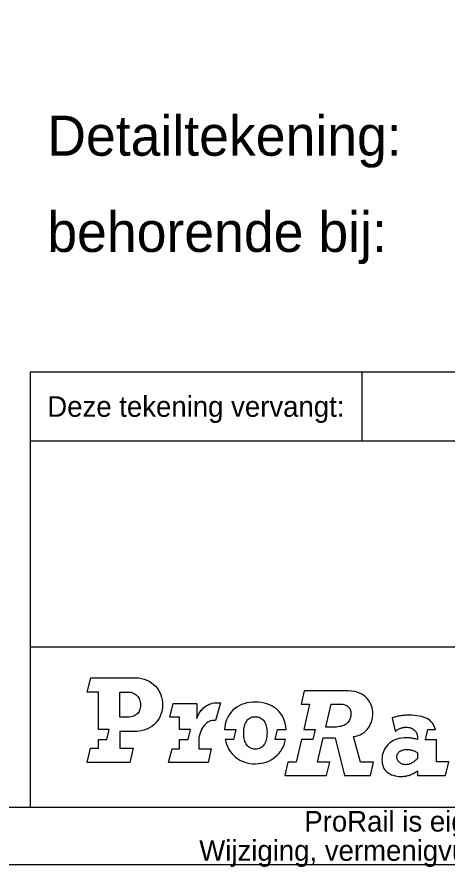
# Model space of a CAD drawing. Extents: x 0 to 1051, y 0 to 297.
# Drawn here: x 864.9 to 902.4, y -0.2 to 74 of the extents above; entities that cross this region are included whole.
import ezdxf

# ---------------------------------------------------------------- set-up
doc = ezdxf.new("R2010")
doc.units = 0
for name, color, linetype in [('KADER-LIJNEN-018', 7, 'Continuous'), ('KADER-LIJNEN-050', 7, 'Continuous'), ('TITEL-DETAIL', 7, 'Continuous'), ('TITEL-LIJNEN-050', 7, 'Continuous'), ('TITEL-PRORAIL', 7, 'Continuous'), ('TITEL-TEKSTEN-018', 7, 'Continuous')]:
    doc.layers.add(name, color=color, linetype=linetype)

msp = doc.modelspace()

# ---------------------------------------------------------------- linework, layer by layer
at = {"layer": 'KADER-LIJNEN-018'}
msp.add_line((0, 0), (1051, 0), dxfattribs=at)
at = {"layer": 'KADER-LIJNEN-050'}
msp.add_lwpolyline([(25, 5), (1046, 5), (1046, 292), (25, 292)], close=True, dxfattribs=at)
at = {"layer": 'TITEL-LIJNEN-050'}
for p, q in [((895, 37), (895, 43)), ((866, 37), (1046, 37)), ((866, 19), (1046, 19))]:
    msp.add_line(p, q, dxfattribs=at)
msp.add_lwpolyline([(866, 5), (1046, 5), (1046, 43), (866, 43)], close=True, dxfattribs=at)
at = {"layer": 'TITEL-PRORAIL'}
for p, q in [((870.991, 15.053), (871.304, 16.306)), ((871.304, 16.306), (875.175, 16.306)), ((875.175, 16.306), (875.456, 16.295)), ((875.456, 16.295), (875.721, 16.257)), ((875.721, 16.257), (875.964, 16.192)), ((875.964, 16.192), (876.196, 16.106)), ((876.196, 16.106), (876.412, 15.998)), ((876.412, 15.998), (876.611, 15.874)), ((876.611, 15.874), (876.79, 15.728)), ((876.79, 15.728), (876.946, 15.571)), ((871.968, 15.053), (870.991, 15.053)), ((871.968, 11.787), (871.968, 15.053)), ((873.826, 15.053), (874.565, 15.053)), ((873.826, 12.856), (873.826, 15.053)), ((874.565, 15.053), (874.679, 15.048)), ((874.679, 15.048), (874.787, 15.037)), ((874.787, 15.037), (874.895, 15.01)), ((874.895, 15.01), (874.992, 14.978)), ((874.992, 14.978), (875.089, 14.934)), ((875.089, 14.934), (875.175, 14.886)), ((875.175, 14.886), (875.262, 14.826)), ((876.946, 15.571), (877.092, 15.399)), ((877.092, 15.399), (877.216, 15.215)), ((877.216, 15.215), (877.324, 15.021)), ((877.324, 15.021), (877.411, 14.816)), ((889.953, 15.161), (889.688, 14.006)), ((893.791, 15.161), (889.953, 15.161)), ((894.067, 15.15), (893.791, 15.161)), ((894.331, 15.113), (894.067, 15.15)), ((894.563, 15.053), (894.331, 15.113)), ((894.779, 14.972), (894.563, 15.053)), ((894.979, 14.875), (894.779, 14.972)), ((895.152, 14.762), (894.979, 14.875)), ((875.262, 14.826), (875.337, 14.756)), ((875.337, 14.756), (875.402, 14.681)), ((875.402, 14.681), (875.461, 14.594)), ((875.461, 14.594), (875.515, 14.502)), ((875.515, 14.502), (875.559, 14.405)), ((875.559, 14.405), (875.591, 14.303)), ((875.591, 14.303), (875.618, 14.189)), ((875.618, 14.189), (875.634, 14.071)), ((877.411, 14.816), (877.475, 14.605)), ((877.475, 14.605), (877.529, 14.394)), ((877.529, 14.394), (877.556, 14.173)), ((877.556, 14.173), (877.567, 13.952)), ((881.913, 14.081), (882.059, 14.108)), ((882.059, 14.108), (882.21, 14.13)), ((882.642, 14.13), (882.205, 12.575)), ((882.21, 14.13), (882.367, 14.13)), ((882.367, 14.13), (882.642, 14.13)), ((884.937, 14.108), (884.705, 14.044)), ((885.18, 14.152), (884.937, 14.108)), ((885.423, 14.179), (885.18, 14.152)), ((885.671, 14.184), (885.423, 14.179)), ((885.936, 14.179), (885.671, 14.184)), ((886.195, 14.146), (885.936, 14.179)), ((886.443, 14.098), (886.195, 14.146)), ((895.309, 14.637), (895.152, 14.762)), ((895.449, 14.497), (895.309, 14.637)), ((895.562, 14.346), (895.449, 14.497)), ((895.665, 14.184), (895.562, 14.346)), ((895.751, 14.017), (895.665, 14.184)), ((875.521, 13.369), (875.467, 13.282)), ((875.564, 13.466), (875.521, 13.369)), ((875.596, 13.574), (875.564, 13.466)), ((875.623, 13.687), (875.596, 13.574)), ((875.634, 13.811), (875.623, 13.687)), ((875.634, 14.071), (875.645, 13.941)), ((875.645, 13.941), (875.634, 13.811)), ((877.535, 13.536), (877.492, 13.325)), ((877.562, 13.741), (877.535, 13.536)), ((877.567, 13.952), (877.562, 13.741)), ((878.204, 12.867), (878.501, 14.054)), ((878.501, 14.054), (880.553, 14.054)), ((880.553, 14.054), (880.553, 12.753)), ((880.861, 13.342), (880.952, 13.466)), ((880.952, 13.466), (881.05, 13.579)), ((881.05, 13.579), (881.152, 13.687)), ((881.152, 13.687), (881.266, 13.779)), ((881.266, 13.779), (881.379, 13.86)), ((881.379, 13.86), (881.503, 13.93)), ((881.503, 13.93), (881.633, 13.99)), ((881.633, 13.99), (881.773, 14.044)), ((881.773, 14.044), (881.913, 14.081)), ((883.69, 13.45), (883.528, 13.271)), ((883.862, 13.606), (883.69, 13.45)), ((884.057, 13.741), (883.862, 13.606)), ((884.262, 13.865), (884.057, 13.741)), ((884.478, 13.963), (884.262, 13.865)), ((884.705, 14.044), (884.478, 13.963)), ((886.681, 14.033), (886.443, 14.098)), ((886.908, 13.952), (886.681, 14.033)), ((887.129, 13.849), (886.908, 13.952)), ((887.329, 13.725), (887.129, 13.849)), ((887.518, 13.585), (887.329, 13.725)), ((887.69, 13.423), (887.518, 13.585)), ((887.847, 13.25), (887.69, 13.423)), ((889.688, 14.006), (890.417, 14.006)), ((890.417, 14.006), (889.909, 11.792)), ((891.821, 12.003), (892.29, 14.006)), ((892.29, 14.006), (893.143, 14.006)), ((893.143, 14.006), (893.235, 14)), ((893.235, 14), (893.327, 13.99)), ((893.327, 13.99), (893.408, 13.973)), ((893.408, 13.973), (893.489, 13.952)), ((893.489, 13.952), (893.57, 13.925)), ((893.57, 13.925), (893.64, 13.887)), ((893.64, 13.887), (893.71, 13.844)), ((893.71, 13.844), (893.77, 13.795)), ((893.77, 13.795), (893.824, 13.741)), ((893.824, 13.741), (893.878, 13.676)), ((893.878, 13.676), (893.921, 13.612)), ((893.921, 13.612), (893.953, 13.536)), ((893.953, 13.536), (893.98, 13.455)), ((893.98, 13.455), (894.002, 13.363)), ((894.002, 13.363), (894.013, 13.271)), ((895.821, 13.849), (895.751, 14.017)), ((895.87, 13.676), (895.821, 13.849)), ((895.908, 13.504), (895.87, 13.676)), ((895.929, 13.331), (895.908, 13.504)), ((874.355, 12.856), (873.826, 12.856)), ((874.517, 12.861), (874.355, 12.856)), ((874.662, 12.877), (874.517, 12.861)), ((874.797, 12.894), (874.662, 12.877)), ((874.927, 12.926), (874.797, 12.894)), ((875.046, 12.964), (874.927, 12.926)), ((875.148, 13.007), (875.046, 12.964)), ((875.246, 13.066), (875.148, 13.007)), ((875.327, 13.126), (875.246, 13.066)), ((875.402, 13.196), (875.327, 13.126)), ((875.467, 13.282), (875.402, 13.196)), ((877.249, 12.726), (877.13, 12.537)), ((877.351, 12.915), (877.249, 12.726)), ((877.427, 13.12), (877.351, 12.915)), ((877.492, 13.325), (877.427, 13.12)), ((879.057, 12.867), (878.204, 12.867)), ((879.057, 11.781), (879.057, 12.867)), ((880.553, 12.753), (880.574, 12.753)), ((880.574, 12.753), (880.634, 12.915)), ((880.634, 12.915), (880.699, 13.066)), ((880.699, 13.066), (880.774, 13.212)), ((880.774, 13.212), (880.861, 13.342)), ((883.155, 12.629), (883.069, 12.37)), ((883.258, 12.861), (883.155, 12.629)), ((883.387, 13.077), (883.258, 12.861)), ((883.528, 13.271), (883.387, 13.077)), ((884.921, 12.537), (884.985, 12.624)), ((884.985, 12.624), (885.061, 12.699)), ((885.061, 12.699), (885.147, 12.764)), ((885.147, 12.764), (885.234, 12.818)), ((885.234, 12.818), (885.336, 12.861)), ((885.336, 12.861), (885.439, 12.888)), ((885.439, 12.888), (885.552, 12.91)), ((885.552, 12.91), (885.671, 12.91)), ((885.671, 12.91), (885.79, 12.91)), ((885.79, 12.91), (885.903, 12.888)), ((885.903, 12.888), (886.006, 12.861)), ((886.006, 12.861), (886.103, 12.818)), ((886.103, 12.818), (886.195, 12.764)), ((886.195, 12.764), (886.281, 12.699)), ((886.281, 12.699), (886.362, 12.629)), ((886.362, 12.629), (886.427, 12.537)), ((887.987, 13.05), (887.847, 13.25)), ((888.106, 12.834), (887.987, 13.05)), ((888.203, 12.602), (888.106, 12.834)), ((893.953, 12.737), (893.905, 12.618)), ((893.986, 12.872), (893.953, 12.737)), ((894.013, 13.012), (893.986, 12.872)), ((894.013, 13.271), (894.018, 13.169)), ((894.018, 13.169), (894.013, 13.012)), ((895.843, 12.537), (895.881, 12.694)), ((895.881, 12.694), (895.913, 12.85)), ((895.913, 12.85), (895.929, 13.007)), ((895.935, 13.158), (895.929, 13.331)), ((895.929, 13.007), (895.935, 13.158)), ((897.706, 12.829), (897.63, 12.791)), ((897.63, 12.791), (897.814, 12.035)), ((897.781, 12.85), (897.706, 12.829)), ((897.862, 12.877), (897.781, 12.85)), ((897.943, 12.899), (897.862, 12.877)), ((898.024, 12.926), (897.943, 12.899)), ((898.111, 12.942), (898.024, 12.926)), ((898.197, 12.958), (898.111, 12.942)), ((898.289, 12.975), (898.197, 12.958)), ((898.381, 12.991), (898.289, 12.975)), ((898.472, 13.002), (898.381, 12.991)), ((898.57, 13.012), (898.472, 13.002)), ((898.672, 13.023), (898.57, 13.012)), ((898.769, 13.029), (898.672, 13.023)), ((898.877, 13.034), (898.769, 13.029)), ((898.98, 13.034), (898.877, 13.034)), ((899.093, 13.034), (898.98, 13.034)), ((899.336, 13.034), (899.093, 13.034)), ((899.568, 13.018), (899.336, 13.034)), ((899.784, 12.996), (899.568, 13.018)), ((899.995, 12.964), (899.784, 12.996)), ((900.184, 12.921), (899.995, 12.964)), ((900.357, 12.867), (900.184, 12.921)), ((900.524, 12.807), (900.357, 12.867)), ((900.67, 12.737), (900.524, 12.807)), ((900.81, 12.651), (900.67, 12.737)), ((900.934, 12.564), (900.81, 12.651)), ((876.428, 11.927), (876.196, 11.819)), ((876.638, 12.057), (876.428, 11.927)), ((876.822, 12.202), (876.638, 12.057)), ((876.989, 12.364), (876.822, 12.202)), ((877.13, 12.537), (876.989, 12.364)), ((881.098, 11.997), (881.012, 11.862)), ((881.19, 12.127), (881.098, 11.997)), ((881.293, 12.24), (881.19, 12.127)), ((881.4, 12.337), (881.293, 12.24)), ((881.519, 12.424), (881.4, 12.337)), ((881.638, 12.489), (881.519, 12.424)), ((881.768, 12.537), (881.638, 12.489)), ((881.903, 12.564), (881.768, 12.537)), ((882.048, 12.575), (881.903, 12.564)), ((882.205, 12.575), (882.048, 12.575)), ((883.015, 12.089), (882.982, 11.792)), ((883.069, 12.37), (883.015, 12.089)), ((884.678, 11.792), (884.699, 11.943)), ((884.699, 11.943), (884.726, 12.084)), ((884.726, 12.084), (884.764, 12.213)), ((884.764, 12.213), (884.807, 12.332)), ((884.807, 12.332), (884.861, 12.44)), ((884.861, 12.44), (884.921, 12.537)), ((886.427, 12.537), (886.492, 12.445)), ((886.492, 12.445), (886.54, 12.337)), ((886.54, 12.337), (886.589, 12.224)), ((886.589, 12.224), (886.627, 12.094)), ((886.627, 12.094), (886.659, 11.96)), ((886.659, 11.96), (886.675, 11.814)), ((888.284, 12.354), (888.203, 12.602)), ((888.338, 12.084), (888.284, 12.354)), ((888.371, 11.792), (888.338, 12.084)), ((892.614, 12.003), (891.821, 12.003)), ((892.755, 12.008), (892.614, 12.003)), ((892.89, 12.019), (892.755, 12.008)), ((893.025, 12.04), (892.89, 12.019)), ((893.154, 12.067), (893.025, 12.04)), ((893.273, 12.1), (893.154, 12.067)), ((893.392, 12.143), (893.273, 12.1)), ((893.5, 12.197), (893.392, 12.143)), ((893.597, 12.262), (893.5, 12.197)), ((893.689, 12.332), (893.597, 12.262)), ((893.77, 12.418), (893.689, 12.332)), ((893.845, 12.51), (893.77, 12.418)), ((893.905, 12.618), (893.845, 12.51)), ((895.433, 11.781), (895.541, 11.916)), ((895.541, 11.916), (895.638, 12.067)), ((895.638, 12.067), (895.719, 12.219)), ((895.719, 12.219), (895.789, 12.375)), ((895.789, 12.375), (895.843, 12.537)), ((897.814, 12.035), (897.911, 11.63)), ((898.3, 11.873), (898.359, 11.9)), ((898.359, 11.9), (898.413, 11.916)), ((898.413, 11.916), (898.472, 11.938)), ((898.472, 11.938), (898.537, 11.954)), ((898.537, 11.954), (898.597, 11.965)), ((898.597, 11.965), (898.661, 11.976)), ((898.661, 11.976), (898.726, 11.986)), ((898.726, 11.986), (898.791, 11.992)), ((898.791, 11.992), (898.861, 11.992)), ((898.861, 11.992), (898.969, 11.986)), ((898.969, 11.986), (899.072, 11.976)), ((899.072, 11.976), (899.169, 11.954)), ((899.169, 11.954), (899.261, 11.927)), ((899.261, 11.927), (899.347, 11.889)), ((899.347, 11.889), (899.433, 11.846)), ((901.042, 12.456), (900.934, 12.564)), ((901.14, 12.348), (901.042, 12.456)), ((901.226, 12.224), (901.14, 12.348)), ((901.301, 12.089), (901.226, 12.224)), ((901.366, 11.943), (901.301, 12.089)), ((901.415, 11.787), (901.366, 11.943)), ((872.892, 11.787), (871.968, 11.787)), ((872.692, 10.907), (872.892, 11.787)), ((875.019, 11.603), (873.826, 11.603)), ((873.826, 11.603), (873.826, 10.167)), ((875.354, 11.619), (875.019, 11.603)), ((875.661, 11.663), (875.354, 11.619)), ((875.942, 11.727), (875.661, 11.663)), ((876.196, 11.819), (875.942, 11.727)), ((880.013, 11.781), (879.057, 11.781)), ((879.808, 10.907), (880.013, 11.781)), ((880.78, 11.209), (880.747, 11.025)), ((880.823, 11.382), (880.78, 11.209)), ((880.871, 11.555), (880.823, 11.382)), ((880.942, 11.711), (880.871, 11.555)), ((881.012, 11.862), (880.942, 11.711)), ((882.982, 11.792), (883.976, 11.792)), ((883.976, 11.792), (883.765, 10.917)), ((884.662, 11.463), (884.667, 11.636)), ((884.667, 11.306), (884.662, 11.463)), ((884.667, 11.636), (884.678, 11.792)), ((884.678, 11.155), (884.667, 11.306)), ((884.699, 11.015), (884.678, 11.155)), ((886.675, 11.177), (886.659, 11.031)), ((886.675, 11.814), (886.692, 11.663)), ((886.692, 11.333), (886.675, 11.177)), ((886.692, 11.663), (886.697, 11.495)), ((886.697, 11.495), (886.692, 11.333)), ((887.393, 10.917), (887.609, 11.792)), ((887.609, 11.792), (888.371, 11.792)), ((889.909, 11.792), (890.897, 11.792)), ((890.897, 11.792), (890.687, 10.917)), ((894.239, 11.166), (894.455, 11.209)), ((894.871, 8.925), (894.239, 11.166)), ((894.455, 11.209), (894.661, 11.263)), ((894.661, 11.263), (894.844, 11.339)), ((894.844, 11.339), (895.017, 11.43)), ((895.017, 11.43), (895.168, 11.533)), ((895.168, 11.533), (895.309, 11.652)), ((895.309, 11.652), (895.433, 11.781)), ((897.911, 11.63), (897.97, 11.673)), ((897.97, 11.673), (898.024, 11.711)), ((898.024, 11.711), (898.078, 11.754)), ((898.078, 11.754), (898.132, 11.787)), ((898.132, 11.787), (898.192, 11.819)), ((898.192, 11.819), (898.246, 11.846)), ((898.246, 11.846), (898.3, 11.873)), ((899.433, 11.846), (899.504, 11.798)), ((899.504, 11.798), (899.574, 11.744)), ((899.574, 11.744), (899.633, 11.679)), ((899.633, 11.679), (899.687, 11.609)), ((899.687, 11.609), (899.73, 11.538)), ((899.73, 11.538), (899.768, 11.452)), ((899.768, 11.452), (899.801, 11.371)), ((899.801, 11.371), (899.822, 11.279)), ((899.822, 11.279), (899.838, 11.187)), ((899.838, 11.187), (899.844, 11.09)), ((900.535, 10.89), (900.756, 11.787)), ((900.756, 11.787), (901.415, 11.787)), ((871.968, 10.167), (871.968, 10.907)), ((871.968, 10.907), (872.686, 10.907)), ((872.686, 10.907), (872.692, 10.907)), ((879.057, 10.091), (879.057, 10.907)), ((879.057, 10.907), (879.802, 10.907)), ((879.802, 10.907), (879.808, 10.907)), ((880.747, 11.025), (880.726, 10.836)), ((880.726, 10.836), (880.726, 10.637)), ((880.726, 10.637), (880.726, 10.091)), ((883.765, 10.917), (883.036, 10.917)), ((883.036, 10.917), (883.09, 10.68)), ((883.09, 10.68), (883.171, 10.448)), ((883.171, 10.448), (883.263, 10.237)), ((884.732, 10.88), (884.699, 11.015)), ((884.764, 10.756), (884.732, 10.88)), ((884.813, 10.642), (884.764, 10.756)), ((884.867, 10.54), (884.813, 10.642)), ((884.931, 10.437), (884.867, 10.54)), ((884.996, 10.356), (884.931, 10.437)), ((886.427, 10.448), (886.362, 10.356)), ((886.492, 10.54), (886.427, 10.448)), ((886.54, 10.648), (886.492, 10.54)), ((886.589, 10.766), (886.54, 10.648)), ((886.627, 10.89), (886.589, 10.766)), ((886.659, 11.031), (886.627, 10.89)), ((888.317, 10.917), (887.393, 10.917)), ((888.095, 10.259), (888.187, 10.464)), ((888.187, 10.464), (888.257, 10.685)), ((888.257, 10.685), (888.317, 10.917)), ((889.715, 10.917), (889.245, 8.925)), ((890.687, 10.917), (889.715, 10.917)), ((891.113, 8.925), (891.605, 11.058)), ((891.605, 11.058), (892.641, 11.058)), ((892.641, 11.058), (893.457, 7.77)), ((897.241, 10.453), (897.128, 10.313)), ((897.376, 10.577), (897.241, 10.453)), ((897.522, 10.685), (897.376, 10.577)), ((897.679, 10.788), (897.522, 10.685)), ((897.851, 10.874), (897.679, 10.788)), ((898.04, 10.944), (897.851, 10.874)), ((898.24, 10.998), (898.04, 10.944)), ((898.451, 11.031), (898.24, 10.998)), ((898.678, 11.052), (898.451, 11.031)), ((898.769, 11.058), (898.678, 11.052)), ((898.85, 11.058), (898.769, 11.058)), ((898.931, 11.063), (898.85, 11.058)), ((899.001, 11.063), (898.931, 11.063)), ((899.066, 11.058), (899.001, 11.063)), ((899.136, 11.058), (899.066, 11.058)), ((899.19, 11.052), (899.136, 11.058)), ((899.255, 11.047), (899.19, 11.052)), ((899.315, 11.036), (899.255, 11.047)), ((899.374, 11.025), (899.315, 11.036)), ((899.439, 11.015), (899.374, 11.025)), ((899.504, 10.998), (899.439, 11.015)), ((899.574, 10.982), (899.504, 10.998)), ((899.655, 10.966), (899.574, 10.982)), ((899.736, 10.944), (899.655, 10.966)), ((899.828, 10.917), (899.736, 10.944)), ((899.844, 11.09), (899.828, 10.917)), ((901.507, 10.89), (900.535, 10.89)), ((901.507, 8.958), (901.507, 10.89)), ((870.991, 8.92), (871.288, 10.167)), ((871.288, 10.167), (871.968, 10.167)), ((873.826, 10.167), (874.997, 10.167)), ((874.997, 10.167), (874.706, 8.92)), ((878.102, 8.909), (878.399, 10.091)), ((878.399, 10.091), (879.057, 10.091)), ((880.726, 10.091), (881.827, 10.091)), ((881.827, 10.091), (881.552, 8.909)), ((883.263, 10.237), (883.371, 10.032)), ((883.371, 10.032), (883.495, 9.843)), ((883.495, 9.843), (883.636, 9.67)), ((883.636, 9.67), (883.792, 9.514)), ((885.072, 10.28), (884.996, 10.356)), ((885.153, 10.221), (885.072, 10.28)), ((885.245, 10.167), (885.153, 10.221)), ((885.342, 10.124), (885.245, 10.167)), ((885.444, 10.097), (885.342, 10.124)), ((885.552, 10.075), (885.444, 10.097)), ((885.671, 10.07), (885.552, 10.075)), ((885.79, 10.075), (885.671, 10.07)), ((885.903, 10.097), (885.79, 10.075)), ((886.006, 10.124), (885.903, 10.097)), ((886.103, 10.167), (886.006, 10.124)), ((886.195, 10.221), (886.103, 10.167)), ((886.281, 10.28), (886.195, 10.221)), ((886.362, 10.356), (886.281, 10.28)), ((887.582, 9.535), (887.734, 9.697)), ((887.734, 9.697), (887.863, 9.87)), ((887.863, 9.87), (887.987, 10.059)), ((887.987, 10.059), (888.095, 10.259)), ((896.804, 9.686), (896.766, 9.508)), ((896.863, 9.854), (896.804, 9.686)), ((896.934, 10.016), (896.863, 9.854)), ((897.025, 10.172), (896.934, 10.016)), ((897.128, 10.313), (897.025, 10.172)), ((898.078, 9.6), (898.1, 9.659)), ((898.1, 9.659), (898.132, 9.719)), ((898.132, 9.719), (898.175, 9.767)), ((898.175, 9.767), (898.219, 9.816)), ((898.219, 9.816), (898.273, 9.865)), ((898.273, 9.865), (898.327, 9.902)), ((898.327, 9.902), (898.391, 9.94)), ((898.391, 9.94), (898.467, 9.973)), ((898.467, 9.973), (898.537, 10)), ((898.537, 10), (898.624, 10.016)), ((898.624, 10.016), (898.705, 10.032)), ((898.705, 10.032), (898.796, 10.043)), ((898.796, 10.043), (898.894, 10.043)), ((898.894, 10.043), (898.942, 10.043)), ((898.942, 10.043), (898.991, 10.043)), ((898.991, 10.043), (899.039, 10.043)), ((899.039, 10.043), (899.093, 10.037)), ((899.093, 10.037), (899.142, 10.032)), ((899.142, 10.032), (899.201, 10.027)), ((899.201, 10.027), (899.255, 10.016)), ((899.255, 10.016), (899.309, 10)), ((899.309, 10), (899.369, 9.983)), ((899.369, 9.983), (899.433, 9.967)), ((899.433, 9.967), (899.493, 9.94)), ((899.493, 9.94), (899.558, 9.919)), ((899.558, 9.919), (899.628, 9.886)), ((899.628, 9.886), (899.698, 9.848)), ((899.698, 9.848), (899.768, 9.811)), ((899.768, 9.811), (899.844, 9.762)), ((899.844, 9.762), (899.844, 9.249)), ((874.706, 8.92), (870.991, 8.92)), ((881.552, 8.909), (878.102, 8.909)), ((883.792, 9.514), (883.954, 9.368)), ((883.954, 9.368), (884.138, 9.238)), ((884.138, 9.238), (884.327, 9.125)), ((884.327, 9.125), (884.527, 9.028)), ((884.527, 9.028), (884.743, 8.947)), ((884.743, 8.947), (884.958, 8.882)), ((886.405, 8.887), (886.632, 8.952)), ((886.632, 8.952), (886.848, 9.039)), ((886.848, 9.039), (887.048, 9.141)), ((887.048, 9.141), (887.237, 9.255)), ((887.237, 9.255), (887.415, 9.39)), ((887.415, 9.39), (887.582, 9.535)), ((888.516, 8.925), (888.241, 7.77)), ((889.245, 8.925), (888.516, 8.925)), ((892.182, 8.925), (891.113, 8.925)), ((891.902, 7.77), (892.182, 8.925)), ((895.994, 8.925), (894.871, 8.925)), ((895.724, 7.77), (895.994, 8.925)), ((896.739, 9.325), (896.734, 9.141)), ((896.734, 9.141), (896.739, 8.974)), ((896.766, 9.508), (896.739, 9.325)), ((896.739, 8.974), (896.761, 8.812)), ((898.046, 9.471), (898.057, 9.535)), ((898.046, 9.4), (898.046, 9.471)), ((898.046, 9.33), (898.046, 9.4)), ((898.057, 9.26), (898.046, 9.33)), ((898.057, 9.535), (898.078, 9.6)), ((898.078, 9.195), (898.057, 9.26)), ((898.1, 9.13), (898.078, 9.195)), ((898.132, 9.071), (898.1, 9.13)), ((898.165, 9.017), (898.132, 9.071)), ((898.213, 8.963), (898.165, 9.017)), ((898.262, 8.914), (898.213, 8.963)), ((898.316, 8.866), (898.262, 8.914)), ((899.412, 8.909), (899.347, 8.871)), ((899.477, 8.952), (899.412, 8.909)), ((899.547, 9.001), (899.477, 8.952)), ((899.612, 9.055), (899.547, 9.001)), ((899.687, 9.114), (899.612, 9.055)), ((899.763, 9.184), (899.687, 9.114)), ((899.844, 9.249), (899.763, 9.184)), ((902.565, 8.958), (901.507, 8.958)), ((902.284, 7.77), (902.565, 8.958)), ((884.958, 8.882), (885.185, 8.833)), ((885.185, 8.833), (885.428, 8.806)), ((885.428, 8.806), (885.671, 8.796)), ((885.671, 8.796), (885.925, 8.812)), ((885.925, 8.812), (886.168, 8.839)), ((886.168, 8.839), (886.405, 8.887)), ((896.761, 8.812), (896.799, 8.666)), ((896.799, 8.666), (896.847, 8.526)), ((896.847, 8.526), (896.912, 8.396)), ((896.912, 8.396), (896.993, 8.277)), ((896.993, 8.277), (897.085, 8.169)), ((897.085, 8.169), (897.187, 8.072)), ((898.375, 8.833), (898.316, 8.866)), ((898.44, 8.796), (898.375, 8.833)), ((898.505, 8.769), (898.44, 8.796)), ((898.58, 8.747), (898.505, 8.769)), ((898.656, 8.731), (898.58, 8.747)), ((898.737, 8.72), (898.656, 8.731)), ((898.818, 8.715), (898.737, 8.72)), ((898.877, 8.72), (898.818, 8.715)), ((898.937, 8.725), (898.877, 8.72)), ((898.996, 8.731), (898.937, 8.725)), ((899.055, 8.747), (898.996, 8.731)), ((899.115, 8.763), (899.055, 8.747)), ((899.169, 8.779), (899.115, 8.763)), ((899.228, 8.806), (899.169, 8.779)), ((899.293, 8.833), (899.228, 8.806)), ((899.347, 8.871), (899.293, 8.833)), ((899.752, 8.115), (899.844, 8.175)), ((899.844, 8.175), (899.844, 7.77)), ((888.241, 7.77), (891.902, 7.77)), ((893.457, 7.77), (895.724, 7.77)), ((897.187, 8.072), (897.306, 7.986)), ((897.306, 7.986), (897.43, 7.91)), ((897.43, 7.91), (897.571, 7.845)), ((897.571, 7.845), (897.727, 7.791)), ((897.727, 7.791), (897.889, 7.748)), ((897.889, 7.748), (898.067, 7.721)), ((898.067, 7.721), (898.251, 7.7)), ((898.251, 7.7), (898.451, 7.694)), ((898.451, 7.694), (898.543, 7.694)), ((898.543, 7.694), (898.634, 7.705)), ((898.634, 7.705), (898.721, 7.71)), ((898.721, 7.71), (898.813, 7.721)), ((898.813, 7.721), (898.894, 7.737)), ((898.894, 7.737), (898.985, 7.759)), ((898.985, 7.759), (899.066, 7.781)), ((899.066, 7.781), (899.153, 7.808)), ((899.153, 7.808), (899.239, 7.84)), ((899.239, 7.84), (899.32, 7.878)), ((899.32, 7.878), (899.406, 7.916)), ((899.406, 7.916), (899.487, 7.959)), ((899.487, 7.959), (899.579, 8.007)), ((899.579, 8.007), (899.66, 8.056)), ((899.66, 8.056), (899.752, 8.115)), ((899.844, 7.77), (902.284, 7.77))]:
    msp.add_line(p, q, dxfattribs=at)

# ---------------------------------------------------------------- texts
at = {"layer": 'TITEL-DETAIL'}
for s, p in [('Detailtekening:', (867.5, 61.9)), ('behorende bij:', (867.5, 53.5))]:
    msp.add_text(s, height=3.5, dxfattribs=at).set_placement(p)
at = {"layer": 'TITEL-TEKSTEN-018'}
for s, p in [('Deze tekening vervangt:', (867.5, 39.1)), ('ProRail is eigenaar van alle digitale en analoge verschijningsvormen van deze tekening en rechthebbende op grond van de Auteurswet 1912.', (889.952, 2.875)), ('Wijziging, vermenigvuldiging en/of openbaarmaking van deze tekening zonder voorafgaande schriftelijke toestemming van ProRail is niet toegestaan.', (880.773, 0.325))]:
    msp.add_text(s, height=1.8, dxfattribs=at).set_placement(p)

doc.saveas('drawing.dxf')
